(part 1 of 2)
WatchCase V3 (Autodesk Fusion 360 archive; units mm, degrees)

design "WatchCase V3" references "Watch Vice Fixture CAD"
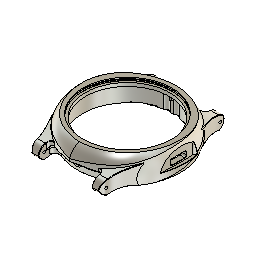
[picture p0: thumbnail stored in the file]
parameter "LugSpacing" = 24
parameter "d280" = 4
sketch "Sketch1"
  line L1 (8, 14) -> (-8, 14)
  line L2 (8, -14) -> (8, 14)
  line L3 (-8, -14) -> (8, -14)
  line L4 (-8, 14) -> (-8, -14)
  line L5 (0, 0) -> (0, 14)
  line L6 (8, 0) -> (0, 0)
  line L7 (0, 14) -> (0, 20.1)
  line L8 (18.5, 5.2) -> (15.5, 5.2)
  line L9 (18.5, -5.2) -> (18.5, 5.2)
  line L10 (15.5, -5.2) -> (18.5, -5.2)
  line L11 (15.5, 5.2) -> (15.5, -5.2)
  line L12 (8, 0) -> (15.5, 0)
  line L13 (19.5, 2.25) -> (18.5, 2.25)
  line L14 (19.5, -2.25) -> (19.5, 2.25)
  line L15 (18.5, -2.25) -> (19.5, -2.25)
  line L16 (19.5, 0.75) -> (18.5, 0.75)
  line L17 (19.5, -0.75) -> (18.5, -0.75)
  line L18 (19.5, 0.75) -> (19.5, -0.75)
  line L19 (18.5, 0) -> (19.5, 0)
  line L20 (-0.8, 20.0841) -> (-0.8, 19.9841)
  line L21 (0.8, 20.0841) -> (0.8, 19.9841)
  circle C1 centre (0, 0) radius 20.1
  circle C2 centre (0, 0) radius 18.85
  circle C3 centre (0, 0) radius 10
  arc A1 centre (0, 19.9841) radius 0.8 clockwise from (0.8, 19.9841) to (-0.8, 19.9841)
  point P4 (-8, 14)
  point P5 (8, 14)
  point P6 (8, -14)
  point P13 (15.5, 5.2)
  point P16 (15.5, -5.2)
  point P14 (18.5, 5.2)
  point P3 (0, 0)
  point P23 (19.5, 0.75)
  point P25 (19.5, -0.75)
  point P29 (0.8, 19.9841)
  point P32 (0.8, 20.0841)
  dimension "d1" diameter C1 = 40.2
  dimension "d3" distance C1 C2 = 1.25
  dimension "d4" diameter C3 = 20
  dimension "d5" distance P4 P5 = 16
  dimension "d6" distance P5 P6 = 28
  dimension "d22" distance P13 P16 = 10.4
  dimension "d23" distance P13 P14 = 3
  dimension "d24" distance P3 L9 = 18.5
  dimension "d25" distance P23 P25 = 1.5
  dimension "d26" distance L13 L16 = 1.5
  dimension "d45" distance P3 = 5.5
  dimension "d108" distance P3 = 1.5
  dimension "d262" distance P3 = 16.5
  dimension "d266" distance P3 = 22
  dimension "d312" radius A1 = 0.8
  dimension "d313" distance P29 P32 = 0.1
  dimension "d464" distance P3 = 27
  dimension "d170" OffsetX = 0
  dimension "d171" OffsetY = 0
  dimension "d172" OffsetZ = 0
  dimension "d173" AngleZ = 0
  dimension "d194" OffsetX = 0
  dimension "d195" OffsetY = 0
  dimension "d196" OffsetZ = 0
  dimension "d197" AngleZ = 0
extrude "Extrude1" new body sketch "Sketch1" profile of C1 C2 L1 L2 L3 L4 C3 L8 L9 L10 L11 L13 L14 L15 L16 L17 L18 A1 L20 L21 blind 1.6 bodies "WatchElectronicsBlank"
extrude "Extrude2" add sketch "Sketch1" profile of L1 L2 L3 L4 C3 blind -5.8
extrude "Extrude3" add sketch "Sketch1" profile of C2 L1 L2 L3 L4 C3 blind 3.1
work_plane "WorkPlane1" AlongDistance -14.2
sketch "Sketch2" plane through (-14.2, 0, 0) normal (1, 0, 0) x axis (0, 1, 0)
  line L1 (3.95, -3) -> (3.95, 0)
  line L2 (-3.95, -3) -> (3.95, -3)
  line L3 (-3.95, 0) -> (-3.95, -3)
  line L4 (3.95, 0) -> (-3.95, 0)
  line L5 (0, -3) -> (0, 0)
  line L6 (-20.1, 0) -> (20.1, 0)
  point P2 (3.95, 0)
  point P5 (-3.95, 0)
  point P4 (-3.95, -3)
  dimension "d18" distance P2 P5 = 7.9
  dimension "d19" distance P4 P5 = 3
extrude "Extrude4" add sketch "Sketch2" profile of L1 L2 L3 L4 L6 against normal blind 6.56
extrude "Extrude5" add sketch "Sketch1" profile of C2 L8 L9 L10 L11 blind -2
extrude "Extrude6" add sketch "Sketch1" profile of C2 L9 L14 L16 L17 L18 blind -1.75 second side blind 1.15 (= "1.75 mm - 0.6 mm")
work_plane "WorkPlane2"
sketch "Sketch3" plane through (0, 0, -1.35) normal (0, 0, 1) x axis (1, 0, 0)
  line L1 (0, -22) -> (0, 1)
  line L2 (0, 22) -> (0, 0)
  line L3 (22, 0) -> (0, 0)
  line L4 (0, 27.5) -> (0, 22)
  line L5
  curve K1 (0, 27.5) -> (0, -27.5)
  curve K2 (-6, 28) -> (6, 27)
  curve K3 (7.7672, -26.1119) -> (-7.7672, -28.8881)
  curve K4 (26, 9) -> (26, -5)
  circle C1 centre (0, 0) radius 19
  circle C2 centre (0, 0) radius 22
  circle C3 centre (0, 0) radius 32
  point P6 (0, -22)
  point P10 (0, -27.5)
  point P8 (0, 22)
  point P11 (0, 27.5)
  dimension "d33" diameter C1 = 38
  dimension "d34" distance C1 C2 = 3
  dimension "d44" distance C2 C3 = 10
  dimension "d45" distance P6 P10 = 5.5
  dimension "d46" distance P8 P11 = 5.5
sketch "Sketch8" plane through (0, 0, -1.35) normal (0, 0, 1) x axis (1, 0, 0)
  curve K1 (0, 27.5) -> (0, -27.5)
  line L1 (0, 27.5) -> (0, 22)
  curve K2 (-5.077, 27.7287) -> (5.077, 27.2713)
  curve K3 (7.4837, -26.6298) -> (-7.4837, -28.3702)
  curve K4 (26.5114, 8) -> (26.5114, -6)
sketch "Sketch6" plane through (0, 0, 0) normal (1, 0, 0) x axis (0, 1, 0)
  line L1 (-22, 4.15) -> (-22, -6.85)
  line L2 (-22, -6.85) -> (-27, -6.85)
  line L3 (-35, -6.85) -> (-27, -6.85)
  line L4 (-35, 4.15) -> (-35, -6.85)
  line L5 (-22, 4.15) -> (-35, 4.15)
  line L6 (22, -6.85) -> (22, 4.15)
  line L7 (35, -6.85) -> (22, -6.85)
  line L8 (35, 4.15) -> (35, -6.85)
  line L9 (22, 4.15) -> (35, 4.15)
  arc A1 centre (-17.2456, -4.6475) radius 10 clockwise from (-27, -6.85) to (-22, 4.15)
  arc A2 centre (15.8225, -0.8201) radius 10 clockwise from (24.5, 4.15) to (23.8, -6.85)
  arc A3 centre (3.71, -0.0109) radius 30 clockwise from (-25.5, -6.85) to (-26, 4.15)
  arc A4 centre (-2.256, -13.4898) radius 30 clockwise from (22.01, 4.15) to (27, -6.85)
  point P2 (-22, -6.85)
  point P3 (-22, 4.15)
  point P9 (-35, 4.15)
  point P15 (24.5, 4.15)
  point P16 (23.8, -6.85)
  point P10 (22, 4.15)
  point P21 (22.01, 4.15)
  point P11 (22, -6.85)
  point P22 (27, -6.85)
  point P19 (-25.5, -6.85)
  point P5 (-27, -6.85)
  point P7 (-22, -6.85)
  point P18 (-26, 4.15)
  dimension "d35" distance P2 P3 = 11
  dimension "d36" distance P3 P9 = 13
  dimension "d37" distance L6 P15 = 2.5
  dimension "d38" distance L6 P16 = 1.8
  dimension "d39" radius A2 = 10
  dimension "d47" radius A4 = 30
  dimension "d48" distance P10 P21 = 0.01
  dimension "d49" distance P11 P22 = 5
  dimension "d54" distance P2 P19 = 3.5
  dimension "d55" distance P5 P7 = 5
  dimension "d56" distance P3 P18 = 4
  dimension "d57" radius A3 = 30
  dimension "d68" radius A1 = 10
extrude "Extrude7" new body sketch "Sketch3" profile of C1 C2 C3 distance 11
loft "Loft1" sketch "Sketch6"
loft "Loft2" sketch "Sketch6"
mirror "Mirror1"
offset_faces "OffsetFaces1" distance -0.3
move "Move1"
combine "Combine1"
extrude "Extrude9" cut of existing geometry no distance stored
extrude "Extrude8" cut of existing geometry no distance stored
extrude "Extrude11" cut of existing geometry no distance stored
offset_faces "OffsetFaces3" distance 0.6
extrude "Extrude13" sketch "Sketch1" profile of C1 C2 L8 L9 L10 L13 L14 L15 L18 A1 L20 L21 blind 0 from offset 1.6
sketch "Sketch19" plane through (0, 0, -0.3) normal (0, 0, -1) x axis (1, 0, 0)
  line L1 (0.8, -19.9841) -> (0.8, -20.0841)
  line L2 (-0.8, -20.0841) -> (-0.8, -19.9841)
  line L3 (0, -18) -> (0, -19.1841)
  line L4 (-0.8, -20.0841) -> (-2.1023, -18.9913)
  arc A1 centre (0, -19.9841) radius 0.8 clockwise from (-0.8, -19.9841) to (0.8, -19.9841)
  arc A2 centre (0, 0) radius 20.1 clockwise from (0.8, -20.0841) to (-0.8, -20.0841)
  circle C1 centre (-2.1023, -18.9913) radius 1.7
  circle C2 centre (0, 0) radius 19
  circle C3 centre (2.1023, -18.9913) radius 1.7
  dimension "d322" diameter C1 = 3.4 (= "( 1.7 * 2 ) * 1 mm")
  dimension "d395" angle L3 L4 = 50
extrude "Extrude31" cut sketch "Sketch19" profile of L1 A1 L2 A2 C1 C2 C3 to an object Side2Offset 0
sketch "Sketch9" plane through (0, 0, 0) normal (1, 0, 0) x axis (0, 1, 0)
  line L1 (-9, 1.7997) -> (-9, -2.573)
  line L2 (-9, -4.2003) -> (-25.2247, -7.3541)
  line L3 (-9, -2.573) -> (-9, -4.2003)
  line L4 (-25.5, -4.2) -> (-25.7828, -4.4828)
  line L5 (-23, -6.9217) -> (-23, -4.2)
  line L6 (-28, -1.7) -> (-25.5, -1.7)
  line L7 (-28, -4.2) -> (-28, -1.7)
  line L8 (-24.3, -4.2) -> (-25.5, -4.2)
  line L9 (-20.5, -0.0538) -> (-20.5, -6.4357)
  line L10 (-22.6313, -6.85) -> (-23, -6.85)
  line L11 (-21.7, -0.3366) -> (-23, -4.2)
  circle C1 centre (-25.7828, -4.4828) radius 0.625
  arc A1 centre (-25.7828, -4.4828) radius 2.925 clockwise from (-25.2247, -7.3541) to (-26.097, -1.5748)
  arc A2 centre (-17.2456, -4.6475) radius 10 clockwise from (-26.2877, -0.3767) to (-22, 4.15)
  arc A3 centre (-36.8383, 97.8467) radius 100 clockwise from (-9, 1.7997) to (-26.097, -1.5748)
  arc A4 centre (-24.2223, -5.1082) radius 4 clockwise from (-28.0184, -6.3691) to (-26.097, -1.5748)
  arc A5 centre (-23.5622, -2.6386) radius 5 clockwise from (-25.2247, -7.3541) to (-28.5028, -3.4071)
  circle C2 centre (-25.5, -4.2) radius 0.625
  circle C3 centre (-25.5, -4.2) radius 2.5
  arc A6 centre (-0.4594, -87.7942) radius 90 clockwise from (-26.6335, -1.6843) to (-9, 1.7997)
  arc A7 centre (-24.2223, -5.1082) radius 4 clockwise from (-26.097, -1.5748) to (-24.8153, -1.1524)
  point P1 (0, 0)
  point P9 (-9, 1.7997)
  point P12 (-9, -4.2003)
  point P13 (-28.0184, -6.3691)
  point P15 (-28.5028, -3.4071)
  point P18 (-25.7828, -4.4828)
  point P19 (-25.5, -4.2)
  point P17 (-25.5, -4.2)
  point P20 (-25.5, -4.2)
  point P22 (-23, -4.2)
  point P36 (-21.7, -0.3366)
  dimension "d71" distance C1 A1 = 2.3
  dimension "d72" diameter C1 = 1.25
  dimension "d74" radius A3 = 100
  dimension "d75" distance P1 P9 = 9
  dimension "d77" angle L2 L3 = 101
  dimension "d78" distance P9 P12 = 6
  dimension "d84" radius A4 = 4
  dimension "d85" distance L2 P13 = 1.5
  dimension "d86" distance L2 P15 = 4.5
  dimension "d87" radius A5 = 5
  dimension "d248" diameter C2 = 1.25
  dimension "d249" distance P18 P19 = 0.4
  dimension "d250" distance P1 P17 = 4.2
  dimension "d251" diameter C3 = 5
  dimension "d291" distance P1 P20 = 25.5
  dimension "d293" angle L4 L8 = 45
  dimension "d296" radius A6 = 90
  dimension "d335" distance L5 L9 = 2.5
  dimension "d342" distance P22 P36 = 1.3
sketch "Sketch15"
  curve K1 (21, -10) -> (14.5, -29)
  curve K2 (16.9276, -20.523) -> (16.0724, -23.477)
  curve K3 (15.7524, -27.1106) -> (13.2476, -30.8894)
  curve K4 (21.5784, -7.8364) -> (20.4216, -12.1636)
  line L1 (12.1, -10) -> (21, -10)
  line L2 (12.1, -29) -> (12.1, -10)
  line L3 (12.1, -29) -> (14.5, -29)
  arc A1 centre (0, 0) radius 20.2 clockwise from (17.5511, -10) to (12.1, -16.175)
  point P1 (0, 0)
  point P3 (16.5, -22)
  point P2 (14.5, -29)
  point P13 (0, 0)
  point P4 (21, -10)
  dimension "d262" distance P1 P3 = 16.5
  dimension "d263" distance P2 P13 = 14.5
  dimension "d264" distance P1 P4 = 21
  dimension "d265" distance P1 P4 = 10
  dimension "d266" distance P1 P3 = 22
  dimension "d267" distance P1 P2 = 29
  dimension "d269" distance P1 L2 = 12.1 (= "( 24.2 / 2 ) * 1 mm")
  dimension "d295" radius A1 = 20.2
extrude "Extrude25" cut sketch "Sketch9" profile of A1 L2 A4 A5 C2 C3 L5 L6 L7 distance 20
extrude "Extrude14" new body sketch "Sketch9" profile of L1 L2 L3 A4 A5 C2 C3 L5 L6 A6 A7 along normal blind 0 and along normal blind 40 bodies "Lug1"
extrude "Extrude26" sketch "Sketch15" profile of K1 L1 L2 L3 blind 10 second side blind 10
work_plane "WorkPlane5" AlongDistance 0.25
mirror "Mirror10"
mirror "Mirror6" bodies "Lug2"
mirror "Mirror8" bodies "Lug3", "Lug4"
extrude "Extrude33" new body sketch "Sketch9" profile of L2 L5 A6 L9 L10 L11 to an object Side2Offset 0
mirror "Mirror12"
chamfer "Chamfer4" distance 2
combine "Combine2" bodies "Lug1", "Lug2", "Lug4", "Lug3"
delete_face "DeleteFace10"
fillet "Fillet33" radius 9
fillet "Fillet30" radius 1.6
fillet "Fillet34" radius 1.6
work_plane "WorkPlane7" AlongDistance 0
sketch "Sketch22" plane through (0, -23, 0) normal (0, -1, 0) x axis (1, 0, 0)
  line L1 (-9.6626, -9.025) -> (-10.2743, -2.0326)
  line L2 (-12.1, -9.025) -> (-9.6626, -9.025)
  line L3 (-12.1, -4.025) -> (-12.1, -9.025)
  line L4 (-7.2621, -8.6017) -> (-9.6626, -9.025)
  line L5 (-8.1304, -3.6777) -> (-7.2621, -8.6017)
  line L6 (-12.1, -3.575) -> (-12.1, -4.825)
  line L7 (-10.1, -4.025) -> (-12.1, -3.6723)
  line L8 (9.7616, -4.2) -> (-9.7616, -4.2)
  arc A1 centre (-10.1, -4.025) radius 2 clockwise from (-12.1, -4.025) to (-10.2743, -2.0326)
  arc A2 centre (-10.1, -4.025) radius 2 clockwise from (-10.2743, -2.0326) to (-8.1304, -3.6777)
  point P4 (-12.1, -9.025)
  point P5 (-12.1, -4.025)
  point P7 (-10.1, -4.025)
  point P11 (-12.1, -4.825)
  dimension "d360" radius A1 = 2
  dimension "d400" distance P4 P5 = 5
  dimension "d401" angle L5 L8 = 80
  dimension "d411" angle L3 L7 = 80
  dimension "d438" distance P7 P11 = 0.8
revolve "Revolve1" sketch "Sketch22" AlongAngle 360
extrude "Extrude36" cut sketch "Sketch22" profile of L1 L2 L3 A1 A2 L4 L5 along normal blind 5
mirror "Mirror14"
work_plane "WorkPlane9"
sketch "Sketch24" plane through (0, 0, 0) normal (0.913, -0.4079, 0) x axis (0.4079, 0.913, 0)
  line L1 (-25.1899, -4.2146) -> (-25.1899, -2.2146)
  line L2 (-27.1899, -9.0313) -> (-27.1899, -2.0313)
  line L3 (-22.7911, -9.0313) -> (-27.1899, -9.0313)
  curve K1 (-22.7911, -6.85) -> (-23.1394, -3.7921)
  line L4 (-25.1194, -2.0313) -> (-27.1899, -2.0313)
  line L5 (-22.7911, -9.0313) -> (-22.7911, -6.85)
  arc A1 centre (-25.1194, -4.025) radius 1.9937 between (-23.1394, -3.7921) and (-25.1347, -2.0314)
  point P3 (-25.1899, -2.2146)
  point P6 (-27.1899, -2.0313)
  point P7 (-27.1899, -9.0313)
  dimension "d404" distance P3 P6 = 2
  dimension "d409" distance P6 P7 = 7
sketch "Sketch25" plane through (0, 0, -6.85) normal (0, 0, -1) x axis (1, 0, 0)
  curve K1 (-22.3111, 9.6073) -> (-11.6625, 21.6672)
  curve K2 (-22.3111, 9.6073) -> (-3.198, -23.1313)
  curve K3 (3.198, -23.1313) -> (22.3111, 9.6073)
  curve K4 (11.6625, 21.6672) -> (22.3111, 9.6073)
  line L1 (-20.16, -3.95) -> (-19.7081, -3.95)
  line L2 (-20.16, 3.95) -> (-20.16, -3.95)
  line L3 (-19.7081, 3.95) -> (-20.16, 3.95)
  line L4 (0, 0) -> (-10.1152, 23)
  line L5 (10.1152, 23) -> (0, 0)
  line L6 (-7.571, 23) -> (7.571, 23)
  line L7 (-9.7871, -23.1313) -> (-3.198, -23.1313)
  curve K5 (-9.7871, -23.1313) -> (-6.9418, -23.5)
  line L8 (6.9418, -23.5) -> (-6.9418, -23.5)
  curve K6 (6.9418, -23.5) -> (9.7871, -23.1313)
  line L9 (3.198, -23.1313) -> (9.7871, -23.1313)
  closed curve K7 centre (9.8355, 23)
  closed curve K8 centre (-9.8355, 23)
  arc A1 centre (-2.1023, -18.9913) radius 1.7 clockwise from (-0.8, -20.0841) to (-3.612, -19.7728)
  arc A2 centre (0, 0) radius 20.1 clockwise from (-3.612, -19.7728) to (-19.7081, -3.95)
  arc A3 centre (2.1023, -18.9913) radius 1.7 clockwise from (3.612, -19.7728) to (0.8, -20.0841)
  closed curve K9 centre (10.1152, 23)
  closed curve K10 centre (-10.1152, 23)
  arc A4 centre (0, 0) radius 20.1 clockwise from (-19.7081, 3.95) to (3.612, -19.7728)
  arc A5 centre (0, 0) radius 20.1 clockwise from (0.8, -20.0841) to (-0.8, -20.0841)
  dimension "d406" angle L4 L5 = 47.479
revolve "Revolve5" sketch "Sketch24" AlongAngle 47.479
mirror "Mirror18"
delete_face "DeleteFace12"
fillet "Fillet22" radius 2
fillet "Fillet21" radius 3
sketch "Sketch10" plane through (0, 0, -6.85) normal (0, 0, -1) x axis (1, 0, 0)
  curve K1 (-22.3111, 9.6073) -> (-16.3714, -16.6945)
  curve K2 (16.3714, -16.6945) -> (22.3111, 9.6073)
  curve K3 (19.5358, 14.633) -> (22.3111, 9.6073)
  line L1 (0, 0) -> (-15.2104, 15.1952)
  line L2 (-5, 0) -> (0, 0)
  line L3 (0, 0) -> (-5, 0)
  line L4 (0, 5) -> (0, 0)
  curve K4 (-22.3111, 9.6073) -> (-19.5358, 14.633)
  curve K5 (11.6625, 21.6672) -> (19.5358, 14.633)
  curve K6 (-19.5358, 14.633) -> (-11.6625, 21.6672)
  curve K7 (9.926, -21.246) -> (16.3714, -16.6945)
  curve K8 (-16.3714, -16.6945) -> (-9.926, -21.246)
  line L5 (-20.16, -3.95) -> (-19.7081, -3.95)
  line L6 (-20.16, 3.95) -> (-20.16, -3.95)
  line L7 (-19.7081, 3.95) -> (-20.16, 3.95)
  curve K9 (8.614, -21.6006) -> (4.8732, -22.764)
  curve K10 (-4.8732, -22.764) -> (-8.614, -21.6006)
  arc A1 centre (0, 0) radius 20.1 clockwise from (-3.612, -19.7728) to (-19.7081, -3.95)
  circle C1 centre (0, 0) radius 21.6
  circle C2 centre (-15.2104, 15.1952) radius 0.625
  arc A2 centre (-14.0183, 18.4859) radius 1.6 clockwise from (-13.0515, 17.211) to (-14.5633, 16.9815)
  arc A3 centre (-15.2104, 15.1952) radius 1.9 clockwise from (-16.9962, 14.5462) to (-14.5633, 16.9815)
  arc A4 centre (-18.5, 13.9997) radius 1.6 clockwise from (-16.9962, 14.5462) to (-17.2241, 13.0342)
  arc A5 centre (14.0183, 18.4859) radius 1.6 clockwise from (14.5633, 16.9815) to (13.0515, 17.211)
  arc A6 centre (15.2104, 15.1952) radius 1.9 clockwise from (14.5633, 16.9815) to (16.9962, 14.5462)
  circle C3 centre (15.2104, 15.1952) radius 0.625
  arc A7 centre (18.5, 13.9997) radius 1.6 clockwise from (17.2241, 13.0342) to (16.9962, 14.5462)
  arc A8 centre (-14.0183, -18.4859) radius 1.6 clockwise from (-14.5633, -16.9815) to (-13.0515, -17.211)
  arc A9 centre (-15.2104, -15.1952) radius 1.9 clockwise from (-14.5633, -16.9815) to (-16.9962, -14.5462)
  arc A10 centre (-18.5, -13.9997) radius 1.6 clockwise from (-17.2241, -13.0342) to (-16.9962, -14.5462)
  circle C4 centre (-15.2104, -15.1952) radius 0.625
  arc A11 centre (15.2104, -15.1952) radius 1.9 clockwise from (16.9962, -14.5462) to (14.5633, -16.9815)
  arc A12 centre (14.0183, -18.4859) radius 1.6 clockwise from (13.0515, -17.211) to (14.5633, -16.9815)
  circle C5 centre (15.2104, -15.1952) radius 0.625
  arc A13 centre (18.5, -13.9997) radius 1.6 clockwise from (16.9962, -14.5462) to (17.2241, -13.0342)
  arc A14 centre (2.1023, -18.9913) radius 1.7 clockwise from (3.612, -19.7728) to (0.8, -20.0841)
  arc A15 centre (-2.1023, -18.9913) radius 1.7 clockwise from (-0.8, -20.0841) to (-3.612, -19.7728)
  circle C6 centre (0, 0) radius 21
  circle C7 centre (0, 0) radius 20.5
  closed curve K11 centre (-9.8355, 23)
  closed curve K12 centre (9.8355, 23)
  arc A16 centre (0, 0) radius 22.7911 clockwise from (-8.614, 21.1006) to (8.614, 21.1006)
  arc A17 centre (0, 0) radius 20.1 clockwise from (-19.7081, 3.95) to (3.612, -19.7728)
  arc A18 centre (0, 0) radius 20.1 clockwise from (0.8, -20.0841) to (-0.8, -20.0841)
  closed curve K13 centre (-9.8355, -23.5)
  closed curve K14 centre (9.8355, -23.5)
  arc A19 centre (0, -0.5) radius 22.7911 clockwise from (4.8732, -22.764) to (-4.8732, -22.764)
  point P17 (0, 0)
  point P18 (-5, 0)
  point P19 (0, 5)
  point P15 (-15.2104, 15.1952)
  point P16 (0, 0)
  dimension "d108" distance A1 C1 = 1.5
  dimension "d109" diameter C2 = 1.25
  dimension "d110" radius A3 = 1.9
  dimension "d112" radius A2 = 1.6
  dimension "d113" distance P17 P18 = 5
  dimension "d114" distance P17 P19 = 5
  dimension "d120" distance P15 P16 = 21.5
  dimension "d330" = 0.5
  dimension "d331" diameter C6 = 42
extrude "Extrude15" cut sketch "Sketch10" profile of A1 C1 C2 A2 A3 A4 A5 A6 C3 A7 A8 A9 A10 C4 A11 A12 C5 A13 against normal blind 1
extrude "Extrude16" cut sketch "Sketch10" profile of C1 C2 C3 C4 C5 against normal blind 4
work_plane "WorkPlane10" AlongDistance 0.175 (= "( 0.35 / 2 ) * 1 mm")
coil_primitive "CoilPrimitive1" Diameter 1.5 SectionSize 0.375 TaperAngle 0 Height 3 Pitch 0.35 bodies "Thread CAM guide1"
circular_pattern "C-Pattern1" TotalAngle 360 bodies "Thread CAM guide2", "Thread CAM guide3", "Thread CAM guide4"
thread "Thread1" ThreadLength 3 ThreadOffset 0
work_plane "WorkPlane11" AlongDistance 6.8
sketch "Sketch32" plane through (0, 0.3738, -5.5) normal (0, 0, -1) x axis (1, 0, 0)
  line L1 (13.5, -18.8762) -> (-13.5, -18.8762)
  line L2 (13.5, 19.6238) -> (13.5, -18.8762)
  line L3 (-13.5, 19.6238) -> (13.5, 19.6238)
  line L4 (-13.5, -18.8762) -> (-13.5, 19.6238)
  line L5 (13.5, 19.6238) -> (-13.5, -18.8762)
  line L6 (-13.5, 19.6238) -> (13.5, -18.8762)
  arc A1 centre (10, -15.3762) radius 3.5 clockwise from (13.5, -15.3762) to (10, -18.8762)
  arc A2 centre (-10, -15.3762) radius 3.5 clockwise from (-10, -18.8762) to (-13.5, -15.3762)
  arc A3 centre (10, 16.1238) radius 3.5 clockwise from (10, 19.6238) to (13.5, 16.1238)
  arc A4 centre (-10, 16.1238) radius 3.5 clockwise from (-13.5, 16.1238) to (-10, 19.6238)
  circle C1 centre (0, 0.3738) radius 19
  point P3 (13.5, -18.8762)
  point P4 (13.5, 19.6238)
  point P2 (-13.5, -18.8762)
  dimension "d462" radius A1 = 3.5
  dimension "d463" distance P3 P4 = 38.5
  dimension "d464" distance P2 P3 = 27
extrude "Extrude38" cut sketch "Sketch32" profile of L1 L2 L3 L4 A1 A2 A3 A4 along normal blind 17
sketch "Sketch11" plane through (0, 0, 4.15) normal (0, 0, 1) x axis (-1, 0, 0)
  curve K1 (19.4592, -12.045) -> (0, -22.01)
  curve K2 (0, 22) -> (19.4592, -12.045)
  curve K3 (-19.4592, -12.045) -> (0, 22)
  curve K4 (0, -22.01) -> (-19.4592, -12.045)
  circle C1 centre (0, 0) radius 19
  circle C2 centre (0, 0) radius 20.05
  circle C3 centre (0, 0) radius 20.65
  dimension "d125" diameter C2 = 40.1
  dimension "d423" diameter C3 = 41.3 (= "40 mm + 0.65 * 2 mm")
extrude "Extrude17" cut sketch "Sketch11" profile of C1 C2 against normal blind 1.3
extrude "Extrude37" sketch "Sketch11" profile of C2 C3 blind 0.75 from offset 0.05
extrude "Extrude18" cut of existing geometry no distance stored
work_plane "WorkPlane3"
sketch "Sketch12" plane through (0, 0, -1.75) normal (0, 0, 1) x axis (-1, 0, 0)
  line L1 (-24.1674, 0.75) -> (-20.086, 0.75)
  curve K1 (-24.1674, 0.75) -> (-24.2538, -0.75)
  line L2 (-20.086, -0.75) -> (-24.2538, -0.75)
  line L3 (-22.75, -10) -> (-22.75, 10)
  line L4 (0, 0) -> (-22.75, 0)
  line L5 (-32.75, -10) -> (-22.75, -10)
  line L6 (-32.75, 10) -> (-32.75, -10)
  line L7 (-22.75, 10) -> (-32.75, 10)
  line L8 (-20.8112, 5) -> (-20.8112, -5)
  line L9 (-10.8112, -5) -> (-20.8112, -5)
  line L10 (-10.8112, 5) -> (-10.8112, -5)
  line L11 (-20.8112, 5) -> (-10.8112, 5)
  line L12 (-22.9169, -7.75) -> (-32.75, -7.75)
  line L13 (-22.9169, 7.75) -> (-32.75, 7.75)
  line L14 (-27.8334, -10) -> (-27.8334, -7.75)
  line L15 (-27.8334, 10) -> (-27.8334, 7.75)
  arc A1 centre (0, 0) radius 20.1 clockwise from (-20.086, -0.75) to (-20.086, 0.75)
  arc A2 centre (96.8326, 0) radius 120 clockwise from (-22.75, -10) to (-22.75, 10)
  arc A3 centre (96.8326, 0) radius 117.75 clockwise from (-20.8112, -5) to (-20.8112, 5)
  arc A4 centre (0, 0) radius 20.1 clockwise from (-3.612, -19.7728) to (3.612, -19.7728)
  arc A5 centre (0, 0) radius 20.1 clockwise from (19.7081, -3.95) to (13.5, -14.8916)
  arc A6 centre (0, 0) radius 20.1 clockwise from (13.5, 14.8916) to (19.7081, 3.95)
  arc A7 centre (0, 0) radius 20.1 clockwise from (-5.7834, 19.25) to (5.7834, 19.25)
  arc A8 centre (0, 0) radius 20.1 clockwise from (5.7834, -19.25) to (3.612, -19.7728)
  arc A9 centre (0, 0) radius 20.1 clockwise from (-3.612, -19.7728) to (-5.7834, -19.25)
  arc A10 centre (0, 0) radius 20.1 clockwise from (-13.5, -14.8916) to (-13.5, 14.8916)
  point P10 (-22.75, 0)
  point P11 (0, 0)
  point P7 (-22.75, -10)
  point P8 (-22.75, 10)
  point P12 (-32.75, -10)
  point P14 (-20.8112, -5)
  point P15 (-20.8112, 5)
  point P17 (-10.8112, -5)
  dimension "d129" radius A2 = 120
  dimension "d130" distance P10 P11 = 22.75
  dimension "d131" distance P7 P8 = 20
  dimension "d132" distance P7 P12 = 10
  dimension "d147" distance P14 P15 = 10
  dimension "d148" distance P14 P17 = 10
  dimension "d153" distance A2 A3 = 2.25
  dimension "d232" distance L12 L13 = 15.5 (= "12 mm + 3.5 mm")
extrude "Extrude19" cut sketch "Sketch12" profile of A2 L6 L7 L12 L13 along normal blind 7 and against normal blind 2
fillet "Fillet13" radius 1.6
extrude "Extrude21" cut sketch "Sketch12" profile of A1 L1 L2 A3 L9 L10 L11 blind 2
fillet "Fillet31" radius 1.7
work_plane "WorkPlane4" AlongDistance 23.124
sketch "Sketch13" plane through (23.124, 0, 0) normal (1, 0, 0) x axis (0, 1, 0)
  line L1 (-3.6, -3.05) -> (-3.6, -0.45)
  line L2 (3.6, -3.05) -> (-3.6, -3.05)
  line L3 (3.6, -0.45) -> (3.6, -3.05)
  line L4 (-3.6, -0.45) -> (3.6, -0.45)
  line L5 (0.75, -1.45) -> (-0.75, -1.45)
  line L6 (-0.75, -2.05) -> (-0.75, -1.45)
  line L7 (-0.75, -1.75) -> (-3.6, -1.75)
  line L8 (0.75, -1.45) -> (0.75, -2.05)
  dimension "d138" distance L4 L5 = 1
  dimension "d139" distance L1 L6 = 2.85
  dimension "d140" distance L3 L8 = 2.85 (= "d139")
  dimension "d247" = 6.5
extrude "Extrude20" cut sketch "Sketch13" profile of L1 L2 L3 L4 along normal blind 1 and against normal blind 10
fillet "Fillet14" radius 0.75
delete_face "DeleteFace9"
fillet "Fillet32" radius 0.5
fillet "Fillet36" radius 0.2
fillet "Fillet37" radius 0.3
chamfer "Chamfer6" distance 0.1
sketch "Sketch33" plane through (0, 0, -5.85) normal (0, 0, -1) x axis (1, 0, 0)
  line L1 (-13.5, 14.7661) -> (-13.5, 15.75)
  line L2 (-13.5, -15.75) -> (-13.5, 14.7661)
  line L3 (13.5, 15.65) -> (13.5, -15.75)
  line L4 (-10, 19.25) -> (10, 19.25)
  line L5 (-10, -19.25) -> (10, -19.25)
  line L6 (12, 17) -> (-12, 17)
  line L7 (12, -17) -> (12, 17)
  line L8 (-12, -17) -> (12, -17)
  line L9 (-12, 17) -> (-12, -17)
  line L10 (12, -17) -> (-12, 17)
  line L11 (-12, -17) -> (12, 17)
  line L12 (3.5, 17) -> (-3.5, 17)
  line L13 (3.5, 20.25) -> (3.5, 17)
  line L14 (-3.5, 20.25) -> (3.5, 20.25)
  line L15 (-3.5, 17) -> (-3.5, 20.25)
  line L16 (0, 20.25) -> (0, 17)
  line L17 (2.5, -10) -> (-2.5, -10)
  line L18 (5, 7.5) -> (5, -7.5)
  line L19 (-2.5, 10) -> (2.5, 10)
  line L20 (-5, -7.5) -> (-5, 7.5)
  line L21 (0, 0) -> (0, -10)
  line L22 (0, 0) -> (-5, 0)
  line L23 (0.625, 9.9) -> (-0.625, 9.9)
  line L24 (0.625, 20.05) -> (0.625, 9.9)
  line L25 (-0.625, 20.05) -> (0.625, 20.05)
  line L26 (-0.625, 9.9) -> (-0.625, 20.05)
  line L27 (0, 10) -> (0, 9.9)
  line L28 (-3.15, 20.05) -> (-4.4, 20.05)
  line L29 (-3.15, 17) -> (-3.15, 20.05)
  line L30 (-4.4, 17) -> (-3.15, 17)
  line L31 (-4.4, 20.05) -> (-4.4, 17)
  curve K1 (12.3, -27.8946) -> (12.1, -27.6297)
  curve K2 (15.5269, -27.711) -> (15.2932, -27.8946)
  curve K3 (18.0172, -17.9868) -> (17.7413, -19.1151)
  curve K4 (20.1194, -13.5027) -> (19.9059, -13.9411)
  curve K5 (15.2932, 27.3946) -> (15.5269, 27.211)
  curve K6 (12.1, 27.1297) -> (12.3, 27.3946)
  curve K7 (-12.3, 27.3946) -> (-12.1, 27.1297)
  curve K8 (-15.5269, 27.211) -> (-15.2932, 27.3946)
  curve K9 (-19.9059, -13.9411) -> (-20.1194, -13.5027)
  curve K10 (-17.7413, -19.1151) -> (-18.0172, -17.9868)
  curve K11 (-15.2932, -27.8946) -> (-15.5269, -27.711)
  curve K12 (-12.1, -27.6297) -> (-12.3, -27.8946)
  line L32 (-9.7978, 19.25) -> (-10, 19.25)
  line L33 (-10, -19.25) -> (-9.7978, -19.25)
  line L34 (9.7978, -19.25) -> (10, -19.25)
  line L35 (10, 19.25) -> (9.7978, 19.25)
  circle C1 centre (-15.2104, 15.1952) radius 0.625
  circle C2 centre (-15.2104, -15.1952) radius 0.625
  circle C3 centre (15.2104, 15.1952) radius 0.625
  circle C4 centre (15.2104, -15.1952) radius 0.625
  arc A1 centre (15.2104, -15.1952) radius 1.9 between (14.5633, -16.9815) and (16.9962, -14.5462)
  arc A2 centre (14.0183, -18.4859) radius 1.6 clockwise from (13.2324, -17.0922) to (14.5633, -16.9815)
  arc A3 centre (18.5, -13.9997) radius 1.6 clockwise from (16.9962, -14.5462) to (17.2241, -13.0342)
  arc A4 centre (0, 0) radius 21.6 between (17.2241, -13.0342) and (17.2241, 13.0342)
  arc A5 centre (18.5, 13.9997) radius 1.6 clockwise from (17.2241, 13.0342) to (16.9962, 14.5462)
  arc A6 centre (15.2104, 15.1952) radius 1.9 between (16.9962, 14.5462) and (14.5633, 16.9815)
  arc A7 centre (14.0183, 18.4859) radius 1.6 clockwise from (14.5633, 16.9815) to (13.2324, 17.0922)
  arc A8 centre (-14.0183, 18.4859) radius 1.6 clockwise from (-13.2324, 17.0922) to (-14.5633, 16.9815)
  arc A9 centre (-15.2104, 15.1952) radius 1.9 between (-14.5633, 16.9815) and (-16.9962, 14.5462)
  arc A10 centre (-18.5, 13.9997) radius 1.6 clockwise from (-16.9962, 14.5462) to (-17.2241, 13.0342)
  arc A11 centre (0, 0) radius 21.6 between (-17.2241, 13.0342) and (-17.2241, -13.0342)
  arc A12 centre (-18.5, -13.9997) radius 1.6 clockwise from (-17.2241, -13.0342) to (-16.9962, -14.5462)
  arc A13 centre (-15.2104, -15.1952) radius 1.9 between (-16.9962, -14.5462) and (-14.5633, -16.9815)
  arc A14 centre (-14.0183, -18.4859) radius 1.6 clockwise from (-14.5633, -16.9815) to (-13.2324, -17.0922)
  arc A15 centre (-10, 15.75) radius 3.5 clockwise from (-13.5, 15.75) to (-10, 19.25)
  arc A16 centre (10, 15.75) radius 3.5 clockwise from (10, 19.25) to (13.5, 15.75)
  arc A17 centre (10, -15.75) radius 3.5 clockwise from (13.5, -15.75) to (10, -19.25)
  arc A18 centre (-10, -15.75) radius 3.5 clockwise from (-10, -19.25) to (-13.5, -15.75)
  arc A19 centre (-5, 10) radius 7 clockwise from (-12, 10) to (-5, 17)
  arc A20 centre (5, 10) radius 7 clockwise from (5, 17) to (12, 10)
  arc A21 centre (-5, -10) radius 7 clockwise from (-5, -17) to (-12, -10)
  arc A22 centre (5, -10) radius 7 clockwise from (12, -10) to (5, -17)
  circle C5 centre (-15.2104, 15.1952) radius 0.85
  circle C6 centre (15.2104, 15.1952) radius 0.85
  circle C7 centre (15.2104, -15.1952) radius 0.85
  circle C8 centre (-15.2104, -15.1952) radius 0.85
  arc A23 centre (-2.5, -7.5) radius 2.5 clockwise from (-2.5, -10) to (-5, -7.5)
  arc A24 centre (2.5, -7.5) radius 2.5 clockwise from (5, -7.5) to (2.5, -10)
  arc A25 centre (2.5, 7.5) radius 2.5 clockwise from (2.5, 10) to (5, 7.5)
  arc A26 centre (-2.5, 7.5) radius 2.5 clockwise from (-5, 7.5) to (-2.5, 10)
  arc A27 centre (0, 0) radius 21.6 between (9.7978, 19.25) and (-9.7978, 19.25)
  arc A28 centre (0, 0) radius 21.6 between (-9.7978, -19.25) and (9.7978, -19.25)
  point P59 (3.5, 20.25)
  point P60 (-3.5, 20.25)
  point P52 (-12, 17)
  point P53 (12, 17)
  point P54 (12, -17)
  point P95 (-0.625, 9.9)
  point P96 (0.625, 9.9)
  point P103 (-3.15, 17)
  point P104 (-4.4, 17)
  dimension "d467" distance P59 P60 = 7
  dimension "d468" distance P52 P53 = 24
  dimension "d469" distance P53 P54 = 34
  dimension "d470" radius A20 = 7
  dimension "d471" distance L4 L14 = 1
  dimension "d474" diameter C5 = 1.7
  dimension "d480" radius A23 = 2.5
  dimension "d481" distance L18 L20 = 10
  dimension "d482" distance L17 L19 = 20
  dimension "d483" distance L4 L25 = 0.8
  dimension "d484" distance L19 L23 = 0.1
  dimension "d485" distance P95 P96 = 1.25
  dimension "d486" distance P103 P104 = 1.25
  dimension "d493" distance L9 L31 = 7.6 (= "9 mm - 1.4 mm")
extrude "Extrude39" new body sketch "Sketch33" profile of A1 A2 A3 A4 A5 A6 A7 A8 A9 A10 A11 A12 A13 A14 A15 A16 A17 A18 L1 L2 L4 L5 L6 L7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 along normal blind 1.5
chamfer "Chamfer5" distance 0.7
extrude "Extrude40" cut sketch "Sketch33" profile of A15 A16 A17 A18 L1 L2 L3 L4 L5 L6 L7 L8 L9 L12 L13 L15 A19 A20 A21 A22 L17 L18 L19 L20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 along normal blind 0.25
extrude "Extrude41" cut sketch "Sketch33" profile of L4 L6 L7 L8 L9 L12 L15 A19 A20 A21 A22 L17 L18 L19 L20 A23 A24 A25 A26 L24 L26 L28 L29 L30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 along normal blind 0.75 (= "1.15 mm - 0.4 mm")
extrude "Extrude42" cut sketch "Sketch33" profile of L4 L6 L12 L19 L23 L24 L25 L26 along normal blind 1.15
offset_faces "OffsetFaces4" distance -0.3
fillet "Fillet35" radius 0.6
sketch "Sketch34" plane through (0, 0, -7.35) normal (0, 0, -1) x axis (1, 0, 0)
  line L1 (-9.7256, -18.95) -> (-10, -18.95)
  line L2 (10, -18.95) -> (9.7256, -18.95)
  line L3 (9.7256, 18.95) -> (10, 18.95)
  line L4 (-10, 18.95) -> (-9.7256, 18.95)
  arc A1 centre (-18.5, -13.9997) radius 1.9 clockwise from (-16.9849, -12.8532) to (-16.7142, -14.6487)
  arc A2 centre (-14.0183, -18.4859) radius 1.9 clockwise from (-14.6655, -16.6995) to (-12.991, -16.8875)
  arc A3 centre (-10, -15.75) radius 3.2 clockwise from (-10, -18.95) to (-12.991, -16.8875)
  arc A4 centre (10, -15.75) radius 3.2 clockwise from (12.991, -16.8875) to (10, -18.95)
  arc A5 centre (14.0183, -18.4859) radius 1.9 clockwise from (12.991, -16.8875) to (14.6655, -16.6995)
  arc A6 centre (18.5, -13.9997) radius 1.9 clockwise from (16.7142, -14.6487) to (16.9849, -12.8532)
  arc A7 centre (0, 0) radius 21.3 clockwise from (16.9849, 12.8532) to (16.9849, -12.8532)
  arc A8 centre (18.5, 13.9997) radius 1.9 clockwise from (16.9849, 12.8532) to (16.7142, 14.6487)
  arc A9 centre (14.0183, 18.4859) radius 1.9 clockwise from (14.6655, 16.6995) to (12.991, 16.8875)
  arc A10 centre (10, 15.75) radius 3.2 clockwise from (10, 18.95) to (12.991, 16.8875)
  arc A11 centre (-10, 15.75) radius 3.2 clockwise from (-12.991, 16.8875) to (-10, 18.95)
  arc A12 centre (-14.0183, 18.4859) radius 1.9 clockwise from (-12.991, 16.8875) to (-14.6655, 16.6995)
  arc A13 centre (-18.5, 13.9997) radius 1.9 clockwise from (-16.7142, 14.6487) to (-16.9849, 12.8532)
  arc A14 centre (0, 0) radius 21.3 clockwise from (-16.9849, -12.8532) to (-16.9849, 12.8532)
  arc A15 centre (-15.2061, 15.2036) radius 6.7075 clockwise from (-21.8981, 14.7483) to (-15.4053, 21.9082)
  arc A16 centre (0, 0) radius 26.4015 clockwise from (-21.8981, -14.7482) to (-21.8981, 14.7483)
  arc A17 centre (-15.206, -15.2036) radius 6.7076 clockwise from (-15.4055, -21.9082) to (-21.8981, -14.7482)
  arc A18 centre (-10, -15.75) radius 8.1941 clockwise from (-11.3951, -23.8244) to (-15.4055, -21.9082)
  arc A19 centre (0.0037, -0.0035) radius 26.4077 clockwise from (11.3937, -23.8286) to (-11.3951, -23.8244)
  arc A20 centre (10, -15.75) radius 8.1979 clockwise from (15.4095, -21.9099) to (11.3937, -23.8286)
  arc A21 centre (15.2055, -15.2046) radius 6.7084 clockwise from (21.8983, -14.7481) to (15.4095, -21.9099)
  arc A22 centre (0, 0) radius 26.4016 clockwise from (21.8981, 14.7484) to (21.8983, -14.7481)
  arc A23 centre (15.2062, 15.2034) radius 6.7074 clockwise from (15.4046, 21.9079) to (21.8981, 14.7484)
  arc A24 centre (10, 15.75) radius 8.1932 clockwise from (11.3939, 23.8238) to (15.4046, 21.9079)
  arc A25 centre (-0.0011, 0.0028) radius 26.4061 clockwise from (-11.3949, 23.8243) to (11.3939, 23.8238)
  arc A26 centre (-10, 15.75) radius 8.1939 clockwise from (-15.4053, 21.9082) to (-11.3949, 23.8243)
  arc A27 centre (15.2104, -15.1952) radius 1.6 clockwise from (16.7142, -14.6487) to (14.6655, -16.6995)
  arc A28 centre (15.2104, 15.1952) radius 1.6 clockwise from (14.6655, 16.6995) to (16.7142, 14.6487)
  arc A29 centre (-15.2104, 15.1952) radius 1.6 clockwise from (-16.7142, 14.6487) to (-14.6655, 16.6995)
  arc A30 centre (-15.2104, -15.1952) radius 1.6 clockwise from (-14.6655, -16.6995) to (-16.7142, -14.6487)
  circle C1 centre (-15.2104, -15.1952) radius 1.55
  circle C2 centre (-15.2104, 15.1952) radius 1.55
  circle C3 centre (15.2104, -15.1952) radius 1.55
  circle C4 centre (15.2104, 15.1952) radius 1.55
  arc A31 centre (0, 0) radius 21.3 clockwise from (-9.7256, 18.95) to (9.7256, 18.95)
  arc A32 centre (0, 0) radius 21.3 clockwise from (9.7256, -18.95) to (-9.7256, -18.95)
sketch "Sketch26"
  line L1 (-28.6909, 32.683) -> (27.1858, 32.683)
  line L2 (-28.6909, -32.183) -> (-28.6909, 32.683)
  line L3 (27.1858, -32.183) -> (-28.6909, -32.183)
  line L4 (27.1858, 32.683) -> (27.1858, -32.183)
  line L5 (23.1858, -7.9065) -> (23.1858, 9.5454)
  curve K1 (-19.5699, 15.0454) -> (-22.3111, -9.6073)
  line L6 (-24.6909, 1.8927) -> (-24.6909, -8.4539)
  line L7 (14.8917, 28.683) -> (12.3, 28.683)
  line L8 (14.8917, -28.183) -> (12.3, -28.183)
  curve K2 (19.4592, 12.045) -> (0, -26.2877)
  curve K3 (9.8007, 22.7919) -> (5.3719, 24.5095)
  curve K4 (23.8121, 7.8449) -> (19.5699, 15.0454)
  curve K5 (22.3111, -9.6073) -> (24.3484, 5.6439)
  point P8 (-22.3111, -9.6073)
  point P11 (-24.6909, 1.8927)
  dimension "d419" distance L4 L5 = 4
  dimension "d420" distance P8 P11 = 11.5
  dimension "d421" distance L2 L6 = 4
  dimension "d496" distance L1 L7 = 4
  dimension "d497" distance L3 L8 = 4
component_insert "Component Insert"
position "Position2"
sketch "Slitting Saw" plane through (0, 0, 0) normal (0, 1, 0) x axis (1, 0, 0)
  line L1 (-5.05, 0) -> (0, 0)
  line L2 (-5.05, -2.4) -> (-5.05, 0)
  line L3 (-9.55, -2.4) -> (-5.05, -2.4)
  line L4 (-9.55, -3.18) -> (-9.55, -2.4)
  line L5 (-8.7, -3.18) -> (-9.55, -3.18)
  line L6 (-8.7, -10.93) -> (-8.7, -3.18)
  line L7 (-3.175, -10.93) -> (-8.7, -10.93)
  line L8 (-3.175, -42.85) -> (-3.175, -10.93)
  line L9 (0, -42.85) -> (-3.175, -42.85)
  line L10 (0, 0) -> (0, -42.85)
  point P2 (0, 0)
  point P3 (-5.05, 0)
  point P4 (-5.05, -2.4)
  point P5 (-9.55, -2.4)
  point P6 (-9.55, -3.18)
  point P7 (-8.7, -3.18)
  point P8 (-8.7, -10.93)
  point P10 (-3.175, -42.85)
  point P11 (0, -42.85)
  point P12 (0, 0)
  dimension "d428" distance P2 P3 = 5.05 (= "( 10.1 / 2 ) * 1 mm")
  dimension "d429" distance P3 P4 = 2.4
  dimension "d430" distance P5 P6 = 0.78
  dimension "d431" distance L4 L10 = 9.55 (= "( 19.1 / 2 ) * 1 mm")
  dimension "d432" distance L6 L10 = 8.7 (= "( 17.4 / 2 ) * 1 mm")
  dimension "d433" distance P7 P8 = 7.75
  dimension "d434" distance P10 P11 = 3.175 (= "( 6.35 / 2 ) * 1 mm")
  dimension "d435" distance P11 P12 = 42.85
sketch "Thread Mill" plane through (0, 0, 0) normal (0, 1, 0) x axis (1, 0, 0)
  line L1 (0.348, 0) -> (0, 0)
  line L2 (0.348, 0.2679) -> (0.58, 0.1339)
  line L3 (1.5, 38) -> (0, 38)
  line L4 (0.58, 0.1339) -> (0.348, 0)
  line L5 (0.348, 3.7679) -> (0.348, 0.2679)
  line L6 (1.5, 4.9199) -> (0.348, 3.7679)
  line L7 (1.5, 4.9199) -> (1.5, 38)
  line L8 (0, 38) -> (0, 0)
  point P1 (0, 0)
  point P2 (0.348, 0)
  point P3 (0.58, 0.1339)
  point P5 (0, 38)
  point P6 (1.5, 38)
  point P7 (0.348, 3.7679)
  point P4 (0.348, 0.2679)
  dimension "d441" distance P1 P2 = 0.348
  dimension "d442" distance L5 L8 = 0.348
  dimension "d443" angle L1 L4 = 30
  dimension "d444" angle L2 L4 = 60
  dimension "d445" distance P3 L8 = 0.58
  dimension "d446" distance P2 P3 = 0.1339
  dimension "d447" distance P1 P5 = 38
  dimension "d448" distance P5 P6 = 1.5
  dimension "d449" distance P1 P7 = 3.7679
  dimension "d451" angle L5 L6 = 45
  dimension "d452" distance P3 P4 = 0.232
mesh "Mesh9"
mesh "Mesh10"
sketch "Sketch35" plane through (0, 0, -7.35) normal (0, 0, -1) x axis (1, 0, 0)
  line L1 (-9.7256, -18.95) -> (-10, -18.95)
  line L2 (10, -18.95) -> (9.7256, -18.95)
  line L3 (9.7256, 18.95) -> (10, 18.95)
  line L4 (-10, 18.95) -> (-9.7256, 18.95)
  arc A1 centre (14.0183, -18.4859) radius 1.9 clockwise from (12.991, -16.8875) to (14.6655, -16.6995)
  arc A2 centre (18.5, -13.9997) radius 1.9 clockwise from (16.7142, -14.6487) to (16.9849, -12.8532)
  arc A3 centre (0, 0) radius 21.3 clockwise from (16.9849, 12.8532) to (16.9849, -12.8532)
  arc A4 centre (18.5, 13.9997) radius 1.9 clockwise from (16.9849, 12.8532) to (16.7142, 14.6487)
  arc A5 centre (14.0183, 18.4859) radius 1.9 clockwise from (14.6655, 16.6995) to (12.991, 16.8875)
  arc A6 centre (10, 15.75) radius 3.2 clockwise from (10, 18.95) to (12.991, 16.8875)
  arc A7 centre (-10, 15.75) radius 3.2 clockwise from (-12.991, 16.8875) to (-10, 18.95)
  arc A8 centre (-14.0183, 18.4859) radius 1.9 clockwise from (-12.991, 16.8875) to (-14.6655, 16.6995)
  arc A9 centre (-18.5, 13.9997) radius 1.9 clockwise from (-16.7142, 14.6487) to (-16.9849, 12.8532)
  arc A10 centre (0, 0) radius 21.3 clockwise from (-16.9849, -12.8532) to (-16.9849, 12.8532)
  arc A11 centre (-18.5, -13.9997) radius 1.9 clockwise from (-16.9849, -12.8532) to (-16.7142, -14.6487)
  arc A12 centre (-14.0183, -18.4859) radius 1.9 clockwise from (-14.6655, -16.6995) to (-12.991, -16.8875)
  arc A13 centre (-10, -15.75) radius 3.2 clockwise from (-10, -18.95) to (-12.991, -16.8875)
  arc A14 centre (10, -15.75) radius 3.2 clockwise from (12.991, -16.8875) to (10, -18.95)
  circle C1 centre (-15.2104, 15.1952) radius 0.85
  circle C2 centre (15.2104, 15.1952) radius 0.85
  circle C3 centre (15.2104, -15.1952) radius 0.85
  circle C4 centre (-15.2104, -15.1952) radius 0.85
  arc A15 centre (15.2104, -15.1952) radius 1.6 clockwise from (16.7142, -14.6487) to (14.6655, -16.6995)
  arc A16 centre (15.2104, 15.1952) radius 1.6 clockwise from (14.6655, 16.6995) to (16.7142, 14.6487)
  arc A17 centre (-15.2104, 15.1952) radius 1.6 clockwise from (-16.7142, 14.6487) to (-14.6655, 16.6995)
  arc A18 centre (-15.2104, -15.1952) radius 1.6 clockwise from (-14.6655, -16.6995) to (-16.7142, -14.6487)
  arc A19 centre (0, 0) radius 21.3 clockwise from (-9.7256, 18.95) to (9.7256, 18.95)
  arc A20 centre (0, 0) radius 21.3 clockwise from (9.7256, -18.95) to (-9.7256, -18.95)
named bodies: "WatchElectronicsBlank", "WatchCase", "Lug3", "Lug1", "Lug2", "Lug4", "Thread CAM guide1", "Thread CAM guide2", "Thread CAM guide3", "Thread CAM guide4", "WatchBack"

design "Watch Vice Fixture CAD"
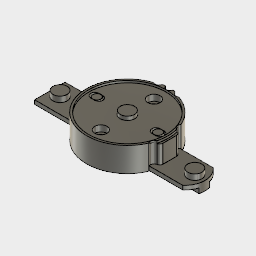
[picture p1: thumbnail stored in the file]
parameter "d90" = 4
parameter "d106" = 4
sketch "Sketch1"
  line L1 (0, 20.2285) -> (0, 20.1)
  line L2 (0, 20.95) -> (0, 20.2285)
  arc A1 centre (0, 0) radius 20.1 clockwise from (19.4682, -5) to (-3.612, 19.7728)
  arc A2 centre (19.1697, -3.3264) radius 1.7 clockwise from (20.869, -3.3751) to (19.4682, -5)
  arc A3 centre (-96.8326, 0) radius 117.75 clockwise from (20.869, 3.3751) to (20.869, -3.3751)
  arc A4 centre (19.1697, 3.3264) radius 1.7 clockwise from (19.4682, 5) to (20.869, 3.3751)
  arc A5 centre (0, 0) radius 20.1 clockwise from (3.612, 19.7728) to (19.4682, 5)
  arc A6 centre (2.1023, 18.9913) radius 1.7 clockwise from (0.8, 20.0841) to (3.612, 19.7728)
  arc A7 centre (0, 0) radius 20.1 clockwise from (-0.8, 20.0841) to (0.8, 20.0841)
  arc A8 centre (-2.1023, 18.9913) radius 1.7 clockwise from (-3.612, 19.7728) to (-0.8, 20.0841)
  arc A9 centre (0, 0) radius 21.6 clockwise from (-17.2241, -13.0342) to (-17.2241, 13.0342)
  arc A10 centre (-18.5, 13.9997) radius 1.6 clockwise from (-16.9962, 14.5462) to (-17.2241, 13.0342)
  arc A11 centre (-15.2104, 15.1952) radius 1.9 clockwise from (-16.9962, 14.5462) to (-14.5633, 16.9815)
  arc A12 centre (-14.0183, 18.4859) radius 1.6 clockwise from (-13.0515, 17.211) to (-14.5633, 16.9815)
  arc A13 centre (0, 0) radius 21.6 clockwise from (-13.0515, 17.211) to (13.0515, 17.211)
  arc A14 centre (14.0183, 18.4859) radius 1.6 clockwise from (14.5633, 16.9815) to (13.0515, 17.211)
  arc A15 centre (15.2104, 15.1952) radius 1.9 clockwise from (14.5633, 16.9815) to (16.9962, 14.5462)
  arc A16 centre (18.5, 13.9997) radius 1.6 clockwise from (17.2241, 13.0342) to (16.9962, 14.5462)
  arc A17 centre (0, 0) radius 21.6 clockwise from (17.2241, 13.0342) to (17.2241, -13.0342)
  arc A18 centre (18.5, -13.9997) radius 1.6 clockwise from (16.9962, -14.5462) to (17.2241, -13.0342)
  arc A19 centre (15.2104, -15.1952) radius 1.9 clockwise from (16.9962, -14.5462) to (14.5633, -16.9815)
  arc A20 centre (14.0183, -18.4859) radius 1.6 clockwise from (13.0515, -17.211) to (14.5633, -16.9815)
  arc A21 centre (0, 0) radius 21.6 clockwise from (13.0515, -17.211) to (-13.0515, -17.211)
  arc A22 centre (-14.0183, -18.4859) radius 1.6 clockwise from (-14.5633, -16.9815) to (-13.0515, -17.211)
  arc A23 centre (-15.2104, -15.1952) radius 1.9 clockwise from (-14.5633, -16.9815) to (-16.9962, -14.5462)
  arc A24 centre (-18.5, -13.9997) radius 1.6 clockwise from (-17.2241, -13.0342) to (-16.9962, -14.5462)
  circle C1 centre (15.2104, 15.1952) radius 0.625
  circle C2 centre (-15.2104, 15.1952) radius 0.625
  circle C3 centre (15.2104, -15.1952) radius 0.625
  circle C4 centre (-15.2104, -15.1952) radius 0.625
  circle C5 centre (5.1662, 20.5772) radius 1.75
  circle C6 centre (-5.1662, 20.5772) radius 1.75
  circle C7 centre (19.7754, 6.7228) radius 1.75
  circle C8 centre (19.7754, -6.7228) radius 1.75
  circle C9 centre (0, 20.1) radius 0.9
  circle C10 centre (0, 20.95) radius 1.75
  arc A25 centre (0, 0) radius 20.1 clockwise from (19.4682, 5) to (19.4682, -5)
  dimension "d6" diameter C8 = 3.5
  dimension "d7" diameter C9 = 1.8
  dimension "d8" diameter C10 = 3.5
extrude "Extrude1" new body sketch "Sketch1" profile of A1 A2 A3 A4 A5 A6 A7 A8 C5 C6 C7 C8 C10 blind 10
extrude "Extrude2" cut sketch "Sketch1" profile of A6 A7 A8 C10 no distance stored
extrude "Extrude3" sketch "Sketch1" profile of A2 A3 A4 A25 blind -1.1
offset_faces "OffsetFaces1" distance -0.1
sketch "Sketch2" plane through (0, 0, 0) normal (1, 0, 0) x axis (0, 1, 0)
  line L1 (-20, 10) -> (19.1, 10)
  line L2 (0, 3) -> (0, 0)
  line L3 (20, 3) -> (-20, 3)
  line L4 (0, 10) -> (0, 3)
  line L5 (-20, 3) -> (-20, 10)
  line L6 (-16, 6) -> (-16, 10)
  line L7 (-14.55, 6) -> (-16, 6)
  line L8 (-14.55, 3) -> (-14.55, 6)
  line L9 (-11.45, 6) -> (-11.45, 3)
  line L10 (-10, 6) -> (-11.45, 6)
  line L11 (-10, 10) -> (-10, 6)
  line L12 (11.45, 6) -> (11.45, 3)
  line L13 (10, 6) -> (11.45, 6)
  line L14 (10, 10) -> (10, 6)
  line L15 (-11.45, 6) -> (-14.55, 6)
  line L16 (-13, 10) -> (-13, 6)
  line L17 (-13, 3) -> (-13, 6)
  line L18 (13, 10) -> (13, 6)
  line L19 (13, 3) -> (13, 6)
  line L20 (-20, 0) -> (19.0241, 0)
  line L21 (-14.25, 0) -> (-14.25, 3)
  line L22 (-13, 0) -> (-13, 3)
  line L23 (-11.75, 0) -> (-11.75, 3)
  line L24 (-11.75, 3) -> (-14.25, 3)
  line L25 (13, 0) -> (13, 3)
  line L26 (11.75, 0) -> (11.75, 3)
  point P10 (-16, 10)
  point P11 (-16, 6)
  point P1 (0, 0)
  dimension "d19" distance P10 P11 = 4
  dimension "d20" distance L8 L9 = 3.1
  dimension "d22" distance L4 L11 = 10
  dimension "d23" distance L6 L11 = 6
  dimension "d24" distance P1 L3 = 3
  dimension "d27" distance L21 L23 = 2.5
  dimension "d28" distance L7 L20 = 6
revolve "Revolve1" sketch "Sketch2" AlongAngle 360
revolve "Revolve2" sketch "Sketch2" AlongAngle 360
work_plane "WorkPlane1" AlongDistance 3
split "Split1" bodies "Clamp Upper"
sketch "Sketch4" plane through (0, 0, 0) normal (0, 1, 0) x axis (1, 0, 0)
  line L1 (-20, 0) -> (20.8174, 0)
  line L2 (20.8174, 4) -> (20.8174, 0)
  line L3 (-20, 4) -> (20.8174, 4)
  line L4 (-20, 0) -> (-20, 4)
  point P4 (20.8174, 0)
  point P5 (20.8174, 4)
  dimension "d41" distance P4 P5 = 4
extrude "Extrude5" add sketch "Sketch4" distance 5.2
delete_face "DeleteFace1"
sketch "Sketch7" plane through (0, 0, 0) normal (0, 0, -1) x axis (1, 0, 0)
  line L1 (20.7887, 2.6) -> (-19.8303, 2.6)
  line L2 (38, 7.5) -> (-38, 7.5)
  line L3 (38, -7.5) -> (38, 7.5)
  line L4 (-38, -7.5) -> (38, -7.5)
  line L5 (-38, 7.5) -> (-38, -7.5)
  line L6 (-19.8303, -2.6) -> (20.7887, -2.6)
  line L7 (-20, 0) -> (-38, 0)
  line L8 (-34.6144, -7.5) -> (-34.6144, 7.5)
  line L9 (0, 7.5) -> (0, 0)
  line L10 (-38, 2.6) -> (-19.8303, 2.6)
  line L11 (-38, -2.6) -> (-19.8303, -2.6)
  line L12 (38, 2.6) -> (20.7887, 2.6)
  line L13 (40.3124, -2.6) -> (20.7887, -2.6)
  arc A1 centre (-96.8326, 0) radius 117.65 clockwise from (20.7691, 3.3723) to (20.7887, 2.6)
  arc A2 centre (19.1697, 3.3264) radius 1.6 clockwise from (19.4506, 4.9016) to (20.7691, 3.3723)
  arc A3 centre (19.7754, 6.7228) radius 1.85 clockwise from (19.4506, 4.9016) to (18.365, 7.92)
  arc A4 centre (0, 0) radius 20 clockwise from (-19.8303, 2.6) to (18.365, 7.92)
  circle C1 centre (0, 13) radius 1.25
  arc A5 centre (0, 0) radius 20 clockwise from (-19.8303, -2.6) to (-19.8303, 2.6)
  circle C2 centre (-33, 0) radius 2.025
  arc A6 centre (-28, 0) radius 10 clockwise from (-34.6144, -7.5) to (-34.6144, 7.5)
  arc A7 centre (28, 0) radius 10 clockwise from (34.6144, 7.5) to (34.6144, -7.5)
  circle C3 centre (33, 0) radius 2.025
  arc A8 centre (5.1662, -20.5772) radius 1.85 clockwise from (3.5232, -19.7268) to (6.1713, -19.0241)
  arc A9 centre (0, 0) radius 20 clockwise from (18.365, -7.92) to (6.1713, -19.0241)
  arc A10 centre (19.7754, -6.7228) radius 1.85 clockwise from (18.365, -7.92) to (19.4506, -4.9016)
  arc A11 centre (19.1697, -3.3264) radius 1.6 clockwise from (20.7691, -3.3723) to (19.4506, -4.9016)
  arc A12 centre (-96.8326, 0) radius 117.65 clockwise from (20.7691, 3.3723) to (20.7691, -3.3723)
  arc A13 centre (19.1697, 3.3264) radius 1.6 clockwise from (19.4506, 4.9016) to (20.7691, 3.3723)
  arc A14 centre (19.7754, 6.7228) radius 1.85 clockwise from (19.4506, 4.9016) to (18.365, 7.92)
  arc A15 centre (0, 0) radius 20 clockwise from (-6.1713, -19.0241) to (18.365, 7.92)
  arc A16 centre (-5.1662, -20.5772) radius 1.85 clockwise from (-6.1713, -19.0241) to (-3.5232, -19.7268)
  arc A17 centre (-2.1023, -18.9913) radius 1.6 clockwise from (-1.8093, -20.5643) to (-3.5232, -19.7268)
  arc A18 centre (0, -20.95) radius 1.85 clockwise from (-1.8093, -20.5643) to (1.8093, -20.5643)
  arc A19 centre (2.1023, -18.9913) radius 1.6 clockwise from (3.5232, -19.7268) to (1.8093, -20.5643)
  circle C4 centre (0, 13) radius 1.55
  circle C5 centre (0, -13) radius 1.55
  point P12 (-38, 7.5)
  point P15 (-38, -7.5)
  point P1 (0, 0)
  point P23 (-33, 0)
  dimension "d73" distance P12 P15 = 15
  dimension "d74" distance P1 P23 = 33
  dimension "d76" radius A6 = 10
  dimension "d77" distance L5 P23 = 5
  dimension "d78" diameter C2 = 4.05
extrude "Extrude14" add sketch "Sketch7" profile of L1 A1 A2 A3 A4 L2 L4 L5 L6 A5 C2 A6 A7 C3 L10 L11 L12 L13 A8 A9 A10 A11 A12 A13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 along normal blind 2
offset_faces "OffsetFaces3" distance 2
extrude "Extrude15" add sketch "Sketch7" profile of L1 L6 A5 C2 A6 A7 C3 L10 L11 L12 L13 A12 A15 along normal blind 4.5
sketch "Sketch3" plane through (0, 0, 0) normal (0, 1, 0) x axis (1, 0, 0)
  line L1 (20, -10) -> (-20, -10)
  line L2 (0, -7) -> (0, 0)
  line L3 (3.6, -8) -> (3.6, -10)
  line L4 (2.1, -8) -> (3.6, -8)
  line L5 (2.1, -7) -> (2.1, -8)
  line L6 (0, -7) -> (2.1, -7)
  line L7 (0, -10) -> (0, -7)
  line L8 (3.6, -10) -> (0, -10)
  line L9 (20.8174, -3) -> (-20, -3)
  line L10 (-22, -7) -> (22, -7)
  line L11 (-22, -1.4022) -> (-22, -7)
  line L12 (22, -1.4022) -> (-22, -1.4022)
  line L13 (22, -7) -> (22, -1.4022)
  point P5 (3.6, -10)
  point P10 (0, -10)
  point P6 (3.6, -8)
  point P7 (2.1, -8)
  point P8 (2.1, -7)
  point P3 (20, -10)
  point P2 (-20, -10)
  dimension "d29" distance L5 L7 = 2.1
  dimension "d30" distance P5 P10 = 3.6
  dimension "d31" distance P5 P6 = 2
  dimension "d32" distance P7 P8 = 1
  dimension "d34" = 1
  dimension "d35" distance P3 L13 = 2
  dimension "d36" distance P2 L11 = 2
